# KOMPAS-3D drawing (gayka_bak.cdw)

Views: Вид 1
Referenced files: Чертеж1.cdw
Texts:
  Гайка
  Текст на чертеже
  Размерные надписи
  Шероховатость
  Линия-выноска #1
  Линия-выноска #2
  Линия-выноска #3
  Отклонения формы и база
  Заголовок таблицы
  Ячейка таблицы
  Стрелка вида
  Обозначение изменения
  Фигурная скобка
  Номер узла
  Марка координационной оси
  VRCB
  Выносная надпись
  Обозначение узла
  Марка/позиционное обозначение с линией-выноской
  Марка/позиционное обозначение на линии
  Марка/позиционное обозначение без линии-выноски
  Symbol type A
  Кв32Х4-7ZA
  Латунь ЛМЦС 58-2-2
Dimensions and other numbers on the sheet: 61 00 Т 02; 7; 3; 50; 43; 4; 4:1; 1; 3.2; 6.3; 2; 1:1; 8; 61 00 Т 02-; 0; 5; 6; 9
